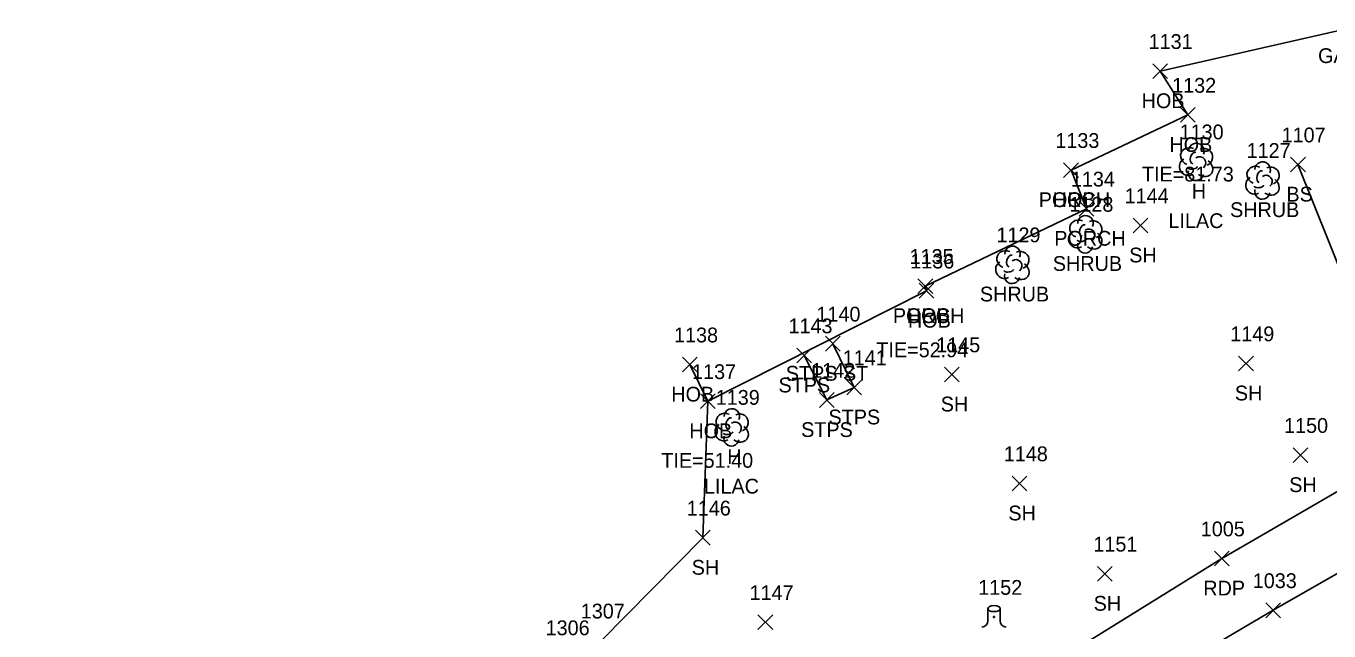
# Model space of a CAD drawing. Extents: x 1526508 to 1531550, y 369926 to 373082.
# Drawn here: x 1530659.9 to 1530836, y 370073.8 to 370155.6 of the extents above; entities that cross this region are included whole.
import ezdxf

# ---------------------------------------------------------------- set-up
doc = ezdxf.new("R2010")
doc.units = 0
for name, color, linetype in [('L_A', 7, 'Continuous'), ('L_C', 7, 'Continuous'), ('L_I', 7, 'Continuous'), ('L_TIC', 7, 'Continuous'), ('LBC', 7, 'Continuous'), ('LBF', 7, 'Continuous'), ('LELB', 7, 'Continuous'), ('LSH', 7, 'Continuous'), ('LSOGP', 7, 'Continuous'), ('LTD', 7, 'Continuous'), ('LTS', 7, 'Continuous'), ('P_A', 7, 'Continuous'), ('P_I', 7, 'Continuous'), ('P_TIC', 7, 'Continuous'), ('PET', 7, 'Continuous'), ('PRC', 7, 'Continuous')]:
    doc.layers.add(name, color=color, linetype=linetype)

msp = doc.modelspace()

# ---------------------------------------------------------------- linework, layer by layer
at = {"layer": 'L_TIC'}
for points in [[(1530812.18, 370148.48), (1530814.18, 370150.48)], [(1530814.18, 370148.48), (1530812.18, 370150.48)], [(1530815.93, 370142.56), (1530817.93, 370144.56)], [(1530817.93, 370142.56), (1530815.93, 370144.56)], [(1530830.81, 370135.85), (1530832.81, 370137.85)], [(1530832.81, 370135.85), (1530830.81, 370137.85)], [(1530800.13, 370135.1), (1530802.13, 370137.1)], [(1530802.13, 370135.1), (1530800.13, 370137.1)], [(1530800.13, 370135.1), (1530802.13, 370137.1)], [(1530802.13, 370135.1), (1530800.13, 370137.1)], [(1530802.23, 370129.88), (1530804.23, 370131.88)], [(1530804.23, 370129.88), (1530802.23, 370131.88)], [(1530809.51, 370127.62), (1530811.51, 370129.62)], [(1530811.51, 370127.62), (1530809.51, 370129.62)], [(1530780.43, 370119.42), (1530782.43, 370121.42)], [(1530782.43, 370119.42), (1530780.43, 370121.42)], [(1530780.43, 370119.42), (1530782.43, 370121.42)], [(1530782.43, 370119.42), (1530780.43, 370121.42)], [(1530780.58, 370118.8), (1530782.58, 370120.8)], [(1530782.58, 370118.8), (1530780.58, 370120.8)], [(1530767.93, 370111.63), (1530769.93, 370113.63)], [(1530769.93, 370111.63), (1530767.93, 370113.63)], [(1530764.06, 370110.04), (1530766.06, 370112.04)], [(1530766.06, 370110.04), (1530764.06, 370112.04)], [(1530823.79, 370108.96), (1530825.79, 370110.96)], [(1530825.79, 370108.96), (1530823.79, 370110.96)], [(1530748.59, 370108.81), (1530750.59, 370110.81)], [(1530750.59, 370108.81), (1530748.59, 370110.81)], [(1530784.03, 370107.47), (1530786.03, 370109.47)], [(1530786.03, 370107.47), (1530784.03, 370109.47)], [(1530770.82, 370105.72), (1530772.82, 370107.72)], [(1530772.82, 370105.72), (1530770.82, 370107.72)], [(1530751.03, 370103.85), (1530753.03, 370105.85)], [(1530753.03, 370103.85), (1530751.03, 370105.85)], [(1530767.12, 370104.02), (1530769.12, 370106.02)], [(1530769.12, 370104.02), (1530767.12, 370106.02)], [(1530831.15, 370096.57), (1530833.15, 370098.57)], [(1530833.15, 370096.57), (1530831.15, 370098.57)], [(1530793.17, 370092.74), (1530795.17, 370094.74)], [(1530795.17, 370092.74), (1530793.17, 370094.74)], [(1530750.36, 370085.4), (1530752.36, 370087.4)], [(1530752.36, 370085.4), (1530750.36, 370087.4)], [(1530804.71, 370080.53), (1530806.71, 370082.53)], [(1530806.71, 370080.53), (1530804.71, 370082.53)], [(1530758.8, 370073.97), (1530760.8, 370075.97)], [(1530760.8, 370073.97), (1530758.8, 370075.97)]]:
    msp.add_lwpolyline(points, dxfattribs=at)
at = {"layer": 'LBC'}
for points in [[(1530813.18, 370149.48), (1530816.93, 370143.56), (1530801.13, 370136.1)], [(1530781.43, 370120.42), (1530781.58, 370119.8), (1530752.03, 370104.85), (1530749.59, 370109.81)]]:
    msp.add_lwpolyline(points, dxfattribs=at)
at = {"layer": 'LBF'}
for points in [[(1530801.13, 370136.1), (1530803.23, 370130.88), (1530781.43, 370120.42)], [(1530768.93, 370112.63), (1530771.82, 370106.72), (1530768.12, 370105.02), (1530765.06, 370111.04)]]:
    msp.add_lwpolyline(points, dxfattribs=at)
at = {"layer": 'LELB'}
msp.add_lwpolyline([(1530831.81, 370136.85), (1530838.22, 370120.82), (1530842.72, 370107.32), (1530845.43, 370104.17), (1530847.94, 370105.74), (1530846.34, 370107.37), (1530844.48, 370108.02), (1530842.31, 370109.68)], dxfattribs=at)
at = {"layer": 'LSH'}
for p, q in [((1530827, 370134.75), (1530827, 370134.75)), ((1530827, 370134.75), (1530827, 370134.75)), ((1530803.04, 370127.47), (1530803.04, 370127.47)), ((1530803.04, 370127.47), (1530803.04, 370127.47)), ((1530793.18, 370123.34), (1530793.18, 370123.34)), ((1530793.18, 370123.34), (1530793.18, 370123.34))]:
    msp.add_line(p, q, dxfattribs=at)
for centre in [(1530827.04, 370136.18), (1530803.08, 370128.91), (1530793.23, 370124.77)]:
    msp.add_arc(centre, 1.05, 335.5272, 180.9563, dxfattribs=at)
for centre, major_axis, ratio, start_param, end_param in [((1530826.2, 370135.42), (1.21, -0.51), 0.895232, 1.570796, 4.712389), ((1530826.79, 370135.21), (-0.208, -0.792), 0.645439, 3.141593, 6.283185), ((1530828.04, 370135.33), (-1.14, -0.48), 0.949671, 1.570796, 4.712389), ((1530825.91, 370134.04), (0.58, -1.04), 0.959034, 3.141593, 6.283185), ((1530826.54, 370134), (-0.625, -0.083), 0.423636, 0, 3.141593), ((1530827.5, 370134.58), (-0.5, 0.667), 0.989748, 3.141593, 6.283185), ((1530828, 370133.92), (-1.09, 0.79), 0.841452, 1.570796, 4.712389), ((1530827, 370133.25), (0.26, 1.06), 0.942809, 1.570796, 4.712389), ((1530802.24, 370128.14), (1.21, -0.51), 0.895232, 1.570796, 4.712389), ((1530802.83, 370127.93), (-0.208, -0.792), 0.645439, 3.141593, 6.283185), ((1530804.08, 370128.06), (-1.14, -0.48), 0.949671, 1.570796, 4.712389), ((1530801.95, 370126.76), (0.58, -1.04), 0.959034, 3.141593, 6.283185), ((1530802.58, 370126.72), (-0.625, -0.083), 0.423636, 0, 3.141593), ((1530803.54, 370127.31), (-0.5, 0.667), 0.989748, 3.141593, 6.283185), ((1530804.04, 370126.64), (-1.09, 0.79), 0.841452, 1.570796, 4.712389), ((1530792.39, 370124.01), (1.21, -0.51), 0.895232, 1.570796, 4.712389), ((1530794.22, 370123.92), (-1.14, -0.48), 0.949671, 1.570796, 4.712389), ((1530803.04, 370125.97), (0.26, 1.06), 0.942809, 1.570796, 4.712389), ((1530792.1, 370122.63), (0.58, -1.04), 0.959034, 3.141593, 6.283185), ((1530792.97, 370123.8), (-0.208, -0.792), 0.645439, 3.141593, 6.283185), ((1530793.68, 370123.17), (-0.5, 0.667), 0.989748, 3.141593, 6.283185), ((1530794.18, 370122.51), (-1.09, 0.79), 0.841452, 1.570796, 4.712389), ((1530793.18, 370121.84), (0.26, 1.06), 0.942809, 1.570796, 4.712389), ((1530792.72, 370122.59), (-0.625, -0.083), 0.423636, 0, 3.141593)]:
    msp.add_ellipse(centre, major_axis=major_axis, ratio=ratio, start_param=start_param, end_param=end_param, dxfattribs=at)
at = {"layer": 'LSOGP'}
msp.add_lwpolyline([(1530839.93, 370155.57), (1530813.18, 370149.48), (1530816.93, 370143.56), (1530801.13, 370136.1), (1530803.23, 370130.88), (1530781.43, 370120.42), (1530781.58, 370119.8), (1530752.03, 370104.85), (1530751.36, 370086.4), (1530737.62, 370072.48)], dxfattribs=at)
at = {"layer": 'LTD'}
for p, q in [((1530818.02, 370137.26), (1530818.02, 370137.26)), ((1530818.02, 370137.26), (1530818.02, 370137.26)), ((1530755.23, 370101.37), (1530755.23, 370101.37)), ((1530755.23, 370101.37), (1530755.23, 370101.37))]:
    msp.add_line(p, q, dxfattribs=at)
for centre in [(1530818.07, 370138.69), (1530755.28, 370102.8)]:
    msp.add_arc(centre, 1.05, 335.5272, 180.9563, dxfattribs=at)
for centre, major_axis, ratio, start_param, end_param in [((1530817.23, 370137.93), (1.21, -0.51), 0.895232, 1.570796, 4.712389), ((1530819.06, 370137.84), (-1.14, -0.48), 0.949671, 1.570796, 4.712389), ((1530816.94, 370136.55), (0.58, -1.04), 0.959034, 3.141593, 6.283185), ((1530817.81, 370137.72), (-0.208, -0.792), 0.645439, 3.141593, 6.283185), ((1530818.52, 370137.09), (-0.5, 0.667), 0.989748, 3.141593, 6.283185), ((1530819.02, 370136.43), (-1.09, 0.79), 0.841452, 1.570796, 4.712389), ((1530818.02, 370135.76), (0.26, 1.06), 0.942809, 1.570796, 4.712389), ((1530817.56, 370136.51), (-0.625, -0.083), 0.423636, 0, 3.141593), ((1530754.44, 370102.03), (1.21, -0.51), 0.895232, 1.570796, 4.712389), ((1530755.02, 370101.83), (-0.208, -0.792), 0.645439, 3.141593, 6.283185), ((1530755.73, 370101.2), (-0.5, 0.667), 0.989748, 3.141593, 6.283185), ((1530756.27, 370101.95), (-1.14, -0.48), 0.949671, 1.570796, 4.712389), ((1530754.15, 370100.66), (0.58, -1.04), 0.959034, 3.141593, 6.283185), ((1530754.77, 370100.62), (-0.625, -0.083), 0.423636, 0, 3.141593), ((1530756.23, 370100.53), (-1.09, 0.79), 0.841452, 1.570796, 4.712389), ((1530755.23, 370099.87), (0.26, 1.06), 0.942809, 1.570796, 4.712389)]:
    msp.add_ellipse(centre, major_axis=major_axis, ratio=ratio, start_param=start_param, end_param=end_param, dxfattribs=at)
at = {"layer": 'LTS'}
for p, q in [((1530789.88, 370076.82), (1530789.88, 370075.15)), ((1530791.55, 370076.65), (1530791.55, 370076.82)), ((1530791.55, 370076.82), (1530791.55, 370075.15)), ((1530790.72, 370075.68), (1530790.72, 370075.68)), ((1530790.72, 370075.68), (1530790.72, 370075.68)), ((1530790.72, 370075.65), (1530790.72, 370075.65))]:
    msp.add_line(p, q, dxfattribs=at)
msp.add_circle((1530790.72, 370075.68), 0.0833, dxfattribs=at)
for centre, start, end in [((1530789.05, 370075.15), 270, 360), ((1530792.38, 370075.15), 180, 270)]:
    msp.add_arc(centre, 0.833, start, end, dxfattribs=at)
msp.add_ellipse((1530790.72, 370076.82), major_axis=(-0.833, 0), ratio=0.5, dxfattribs=at)
at = {"layer": 'P_TIC'}
for points in [[(1530820.52, 370082.59), (1530822.52, 370084.59)], [(1530822.52, 370082.59), (1530820.52, 370084.59)], [(1530827.47, 370075.59), (1530829.47, 370077.59)], [(1530829.47, 370075.59), (1530827.47, 370077.59)]]:
    msp.add_lwpolyline(points, dxfattribs=at)
at = {"layer": 'PET'}
msp.add_lwpolyline([(1530659.86, 369987.59), (1530689.68, 370004.88), (1530725.77, 370025.63), (1530760.95, 370046.59), (1530789.35, 370063.64), (1530821.52, 370083.59), (1530847.47, 370098.66), (1530877.57, 370115.25), (1530907.84, 370128.26), (1530938.81, 370136.76), (1530967.77, 370140.97), (1531005.44, 370146.08), (1531034.99, 370150.93)], dxfattribs=at)
at = {"layer": 'PRC'}
msp.add_lwpolyline([(1530664.43, 369978.53), (1530688.65, 369992.9), (1530715.76, 370008.79), (1530744.4, 370025.81), (1530774.39, 370044.32), (1530799.13, 370059.29), (1530828.47, 370076.59), (1530863.72, 370096.73), (1530899.64, 370113.89), (1530935.78, 370125.96), (1530974.77, 370132.27), (1531009.67, 370136.56), (1531036.22, 370140.48)], dxfattribs=at)

# ---------------------------------------------------------------- texts
at = {"layer": 'L_A'}
for s, p in [('GARAGE', (1530834.53, 370150.57)), ('HOB', (1530810.68, 370144.48)), ('HOB', (1530814.43, 370138.56)), ('H', (1530817.45, 370132.26)), ('BS', (1530830.25, 370131.85)), ('PORCH', (1530796.76, 370131.1)), ('HOB', (1530798.64, 370131.1)), ('SHRUB', (1530822.63, 370129.75)), ('PORCH', (1530798.86, 370125.88)), ('SH', (1530809, 370123.62)), ('SHRUB', (1530798.67, 370122.47)), ('SHRUB', (1530788.81, 370118.34)), ('PORCH', (1530777.05, 370115.42)), ('HOB', (1530778.93, 370115.42)), ('HOB', (1530779.09, 370114.8)), ('STPS ST', (1530762.57, 370107.63)), ('STPS', (1530761.58, 370106.04)), ('HOB', (1530747.09, 370104.81)), ('SH', (1530823.28, 370104.96)), ('SH', (1530783.52, 370103.47)), ('STPS', (1530768.34, 370101.72)), ('HOB', (1530749.53, 370099.85)), ('STPS', (1530764.64, 370100.02)), ('H', (1530754.66, 370096.37)), ('SH', (1530830.63, 370092.57)), ('SH', (1530792.66, 370088.74)), ('SH', (1530749.85, 370081.4)), ('SH', (1530804.19, 370076.53))]:
    msp.add_text(s, height=2, dxfattribs=at).set_placement(p)
at = {"layer": 'L_C'}
for s, p in [('TIE=81.73', (1530810.72, 370134.56)), ('LILAC', (1530814.3, 370128.26)), ('TIE=52.94', (1530774.81, 370110.8)), ('TIE=51.40', (1530745.74, 370095.85)), ('LILAC', (1530751.51, 370092.37))]:
    msp.add_text(s, height=2, dxfattribs=at).set_placement(p)
at = {"layer": 'L_I'}
for s, p in [('1131', (1530811.62, 370152.48)), ('1132', (1530814.8, 370146.56)), ('1133', (1530799.01, 370139.1)), ('1133', (1530799.01, 370139.1)), ('1130', (1530815.81, 370140.26)), ('1107', (1530829.6, 370139.85)), ('1127', (1530824.87, 370137.75)), ('1134', (1530801.11, 370133.88)), ('1128', (1530800.91, 370130.47)), ('1144', (1530808.38, 370131.62)), ('1129', (1530791.05, 370126.34)), ('1135', (1530779.3, 370123.42)), ('1135', (1530779.3, 370123.42)), ('1136', (1530779.4, 370122.8)), ('1140', (1530766.71, 370115.63)), ('1138', (1530747.46, 370112.81)), ('1143', (1530762.93, 370114.04)), ('1149', (1530822.66, 370112.96)), ('1145', (1530782.9, 370111.47)), ('1141', (1530770.26, 370109.72)), ('1137', (1530749.9, 370107.85)), ('1142', (1530766, 370108.02)), ('1139', (1530753.1, 370104.37)), ('1150', (1530829.93, 370100.57)), ('1148', (1530792.04, 370096.74)), ('1146', (1530749.18, 370089.4)), ('1151', (1530804.15, 370084.53)), ('1147', (1530757.67, 370077.97)), ('1152', (1530788.58, 370078.68)), ('1307', (1530734.85, 370075.48)), ('1306', (1530730.1, 370073.22))]:
    msp.add_text(s, height=2, dxfattribs=at).set_placement(p)
at = {"layer": 'P_A'}
msp.add_text('RDP', height=2, dxfattribs=at).set_placement((1530819.01, 370078.59))
at = {"layer": 'P_I'}
for s, p in [('1005', (1530818.67, 370086.59)), ('1033', (1530825.7, 370079.59))]:
    msp.add_text(s, height=2, dxfattribs=at).set_placement(p)

doc.saveas('drawing.dxf')
